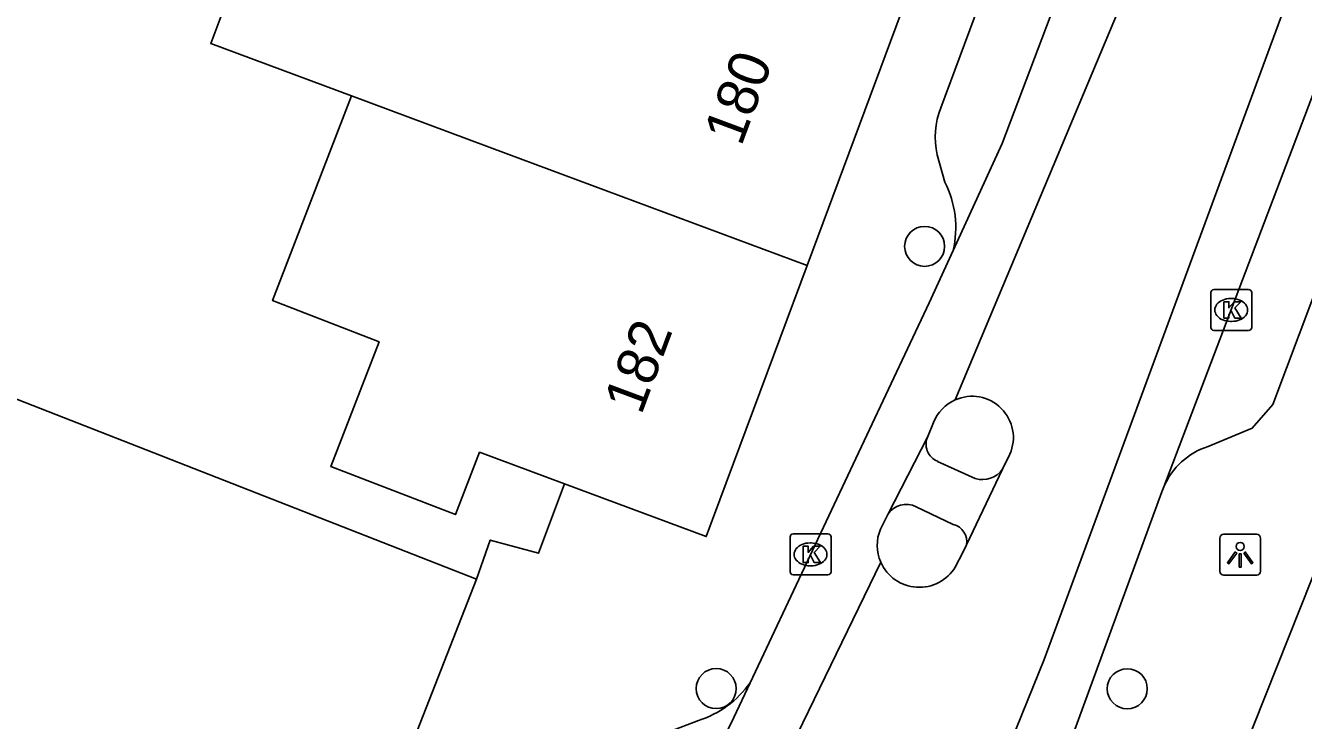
# Model space of a CAD drawing. Extents: x 160356 to 161355, y 381727 to 382845.
# Drawn here: x 160681.56 to 160712.78, y 382017.41 to 382034.4 of the extents above; entities that cross this region are included whole.
import ezdxf

# ---------------------------------------------------------------- set-up
doc = ezdxf.new("R2010")
doc.units = 0
for name, color, linetype in [('IMGEO_Boom', 7, 'Continuous'), ('IMGEO_Kolk', 7, 'Continuous'), ('IMGEO_Lichtpunt', 7, 'Continuous'), ('IMGEO_Pand', 7, 'Continuous'), ('IMGEO_Pand_nummerreeks', 7, 'Continuous'), ('IMGEO_Rijbaan_lokaal_gesloten', 7, 'Continuous'), ('IMGEO_Voetpad_open', 7, 'Continuous')]:
    doc.layers.add(name, color=color, linetype=linetype)

msp = doc.modelspace()

# ---------------------------------------------------------------- linework, layer by layer
at = {"layer": 'IMGEO_Boom'}
for centre in [(160703.526, 382029.002), (160698.432, 382018.193), (160708.478, 382018.188)]:
    msp.add_circle(centre, 0.489, dxfattribs=at)
at = {"layer": 'IMGEO_Kolk'}
for p, q in [((160710.593, 382027.947), (160711.445, 382027.947)), ((160710.518, 382027.021), (160710.518, 382027.873)), ((160711.006, 382027.727), (160711.031, 382027.727)), ((160711.519, 382027.873), (160711.519, 382027.021)), ((160711.029, 382027.167), (160711.004, 382027.167)), ((160711.445, 382026.947), (160710.593, 382026.947)), ((160700.238, 382021.047), (160700.238, 382021.899)), ((160700.313, 382021.973), (160701.165, 382021.973)), ((160700.726, 382021.753), (160700.751, 382021.753)), ((160701.239, 382021.899), (160701.239, 382021.047)), ((160700.749, 382021.193), (160700.724, 382021.193)), ((160701.165, 382020.973), (160700.313, 382020.973))]:
    msp.add_line(p, q, dxfattribs=at)
for points in [[(160710.593, 382027.947), (160711.445, 382027.947)], [(160710.518, 382027.021), (160710.518, 382027.873)], [(160710.839, 382027.647), (160710.962, 382027.647), (160710.962, 382027.496), (160711.092, 382027.647), (160711.256, 382027.647), (160711.11, 382027.496), (160711.263, 382027.247), (160711.111, 382027.247), (160711.026, 382027.411), (160710.962, 382027.344), (160710.962, 382027.247), (160710.839, 382027.247), (160710.839, 382027.647)], [(160711.519, 382027.873), (160711.519, 382027.021)], [(160711.445, 382026.947), (160710.593, 382026.947)], [(160700.238, 382021.047), (160700.238, 382021.899)], [(160700.313, 382021.973), (160701.165, 382021.973)], [(160701.239, 382021.899), (160701.239, 382021.047)], [(160700.559, 382021.673), (160700.682, 382021.673), (160700.682, 382021.522), (160700.812, 382021.673), (160700.976, 382021.673), (160700.83, 382021.522), (160700.983, 382021.273), (160700.831, 382021.273), (160700.746, 382021.437), (160700.682, 382021.37), (160700.682, 382021.273), (160700.559, 382021.273), (160700.559, 382021.673)], [(160701.165, 382020.973), (160700.313, 382020.973)]]:
    msp.add_lwpolyline(points, dxfattribs=at)
for centre, start, end in [((160710.595, 382027.871), 91.552, 178.448), ((160710.595, 382027.871), 91.552, 178.448), ((160711.443, 382027.871), 1.552, 88.448), ((160711.443, 382027.871), 1.552, 88.448), ((160710.595, 382027.023), 181.552, 268.448), ((160710.595, 382027.023), 181.552, 268.448), ((160711.443, 382027.023), 271.552, 358.448), ((160711.443, 382027.023), 271.552, 358.448), ((160700.315, 382021.897), 91.552, 178.448), ((160700.315, 382021.897), 91.552, 178.448), ((160701.163, 382021.897), 1.552, 88.448), ((160701.163, 382021.897), 1.552, 88.448), ((160700.315, 382021.049), 181.552, 268.448), ((160700.315, 382021.049), 181.552, 268.448), ((160701.163, 382021.049), 271.552, 358.448), ((160701.163, 382021.049), 271.552, 358.448)]:
    msp.add_arc(centre, 0.0765, start, end, dxfattribs=at)
for centre, major_axis, ratio, start_param, end_param in [((160711.005, 382027.447), (-0.387, 0.002), 0.722429, 4.712389, 7.853982), ((160711.03, 382027.447), (-0.39, 0.002), 0.717154, 1.570796, 4.712389), ((160700.725, 382021.473), (-0.387, 0.002), 0.722429, 4.712389, 7.853982), ((160700.75, 382021.473), (-0.39, 0.002), 0.717154, 1.570796, 4.712389)]:
    msp.add_ellipse(centre, major_axis=major_axis, ratio=ratio, start_param=start_param, end_param=end_param, dxfattribs=at)
at = {"layer": 'IMGEO_Lichtpunt'}
for p, q in [((160710.739, 382021.869), (160710.739, 382021.062)), ((160710.739, 382021.869), (160710.739, 382021.062)), ((160711.641, 382021.964), (160710.833, 382021.964)), ((160711.641, 382021.964), (160710.833, 382021.964)), ((160711.735, 382021.062), (160711.735, 382021.869)), ((160711.735, 382021.062), (160711.735, 382021.869)), ((160710.833, 382020.968), (160711.641, 382020.968)), ((160710.833, 382020.968), (160711.641, 382020.968))]:
    msp.add_line(p, q, dxfattribs=at)
for points in [[(160711.113, 382021.533), (160711.152, 382021.505), (160710.964, 382021.243), (160710.926, 382021.27), (160711.113, 382021.533)], [(160711.215, 382021.485), (160711.262, 382021.485), (160711.262, 382021.163), (160711.215, 382021.163), (160711.215, 382021.485)], [(160711.325, 382021.505), (160711.363, 382021.532), (160711.55, 382021.27), (160711.511, 382021.242), (160711.325, 382021.505)]]:
    msp.add_lwpolyline(points, dxfattribs=at)
msp.add_circle((160711.238, 382021.667), 0.0994, dxfattribs=at)
for centre, start, end in [((160710.833, 382021.869), 90, 180), ((160710.833, 382021.869), 90, 180), ((160711.641, 382021.869), 0, 90), ((160711.641, 382021.869), 0, 90), ((160710.833, 382021.062), 180, 270), ((160710.833, 382021.062), 180, 270), ((160711.641, 382021.062), 270, 0), ((160711.641, 382021.062), 270, 360)]:
    msp.add_arc(centre, 0.0946, start, end, dxfattribs=at)
at = {"layer": 'IMGEO_Pand'}
for points in [[(160660.842, 382040.237), (160659.757, 382037.624), (160654.494, 382039.809), (160653.852, 382036.7), (160654.668, 382036.531), (160653.948, 382033.048), (160653.21, 382033.201), (160652.031, 382030.186), (160664.979, 382025.121), (160667.199, 382030.796), (160678.768, 382026.27), (160684.128, 382024.173), (160692.577, 382020.868)], [(160691.727, 382039.294), (160690.193, 382035.169), (160688.694, 382035.727), (160686.815, 382035.925), (160686.083, 382033.957), (160689.52, 382032.679)], [(160700.657, 382028.536), (160703.087, 382035.068)], [(160689.52, 382032.679), (160687.591, 382027.678), (160690.197, 382026.672), (160689.019, 382023.617), (160692.06, 382022.444), (160692.649, 382023.969), (160694.723, 382023.198)], [(160700.657, 382028.536), (160693.3, 382031.273), (160689.52, 382032.679)], [(160694.723, 382023.198), (160698.192, 382021.908), (160700.657, 382028.536)], [(160686.323, 382008.467), (160687.207, 382010.728), (160688.566, 382014.202), (160687.548, 382014.601), (160688.056, 382015.9), (160690.292, 382015.025), (160690.483, 382015.514), (160692.577, 382020.868)]]:
    msp.add_lwpolyline(points, dxfattribs=at)
at = {"layer": 'IMGEO_Rijbaan_lokaal_gesloten'}
for points in [[(160704.275, 382025.25), (160710.123, 382039.204), (160720.494, 382066.374), (160724.887, 382077.653), (160727.444, 382083.882), (160731.871, 382093.997), (160742.756, 382117.768), (160747.076, 382126.71), (160748.813, 382130.153), (160751.633, 382135.727), (160755.42, 382142.776), (160760.731, 382152.677), (160766.428, 382162.546), (160770.494, 382169.628), (160769.164, 382170.249)], [(160774.485, 382166.436), (160773.018, 382167.169), (160767.084, 382156.956), (160759.953, 382144.071), (160758.33, 382141.071), (160754.903, 382134.448), (160748.477, 382121.661), (160743.231, 382110.677), (160737.526, 382098.251), (160733.461, 382089.005), (160728.018, 382076.284), (160718.969, 382052.415), (160712.871, 382036.35), (160706.444, 382018.907), (160701.297, 382006.186), (160702.724, 382005.472)], [(160747.213, 382130.437), (160738.5, 382112.538), (160731.504, 382097.136), (160724.098, 382079.993), (160717.39, 382062.79), (160711.373, 382047.241), (160705.42, 382031.515), (160704.223, 382028.902)], [(160709.375, 382023.124), (160713.284, 382033.416), (160713.707, 382034.733), (160721.146, 382054.264)], [(160704.223, 382028.902), (160703.636, 382027.62), (160699.26, 382018.335)], [(160703.607, 382024.358), (160703.747, 382024.699)], [(160702.626, 382022.447), (160703.607, 382024.358)], [(160705.433, 382023.557), (160705.609, 382023.921)], [(160705.433, 382023.557), (160704.546, 382021.704)], [(160704.168, 382009.251), (160704.765, 382010.743), (160706.286, 382014.7), (160709.327, 382022.999), (160709.375, 382023.124)], [(160702.448, 382022.093), (160702.626, 382022.447)], [(160704.275, 382021.164), (160704.459, 382021.523), (160704.546, 382021.704)], [(160693.954, 382007.485), (160695.412, 382006.702), (160700.139, 382016.515), (160702.456, 382021.28)], [(160699.26, 382018.335), (160698.861, 382017.487), (160693.954, 382007.485)]]:
    msp.add_lwpolyline(points, dxfattribs=at)
for centre, radius, start, end in [((160704.688, 382024.325), 1.013, 114.0907, 158.3515), ((160704.685, 382024.327), 1.01, 336.2562, 113.9589), ((160703.394, 382021.696), 1.026, 157.2139, 203.9137), ((160703.396, 382021.696), 1.028, 203.8879, 328.8144)]:
    msp.add_arc(centre, radius, start, end, dxfattribs=at)
at = {"layer": 'IMGEO_Voetpad_open'}
for points in [[(160707.027, 382005.872), (160723.769, 382047.981), (160723.909, 382047.851), (160734.483, 382073.75), (160746.148, 382100.741), (160750.887, 382111.2), (160755.847, 382121.079), (160757.838, 382125.044), (160765.277, 382139.388)], [(160703.919, 382032.385), (160710.641, 382050.478), (160716.296, 382065.22), (160720.616, 382076.203), (160724.822, 382086.526), (160726.382, 382090.148)], [(160721.637, 382050.795), (160714.942, 382032.865), (160712.034, 382025.14), (160711.531, 382024.56), (160710.453, 382024.108)], [(160704.02, 382030.569), (160703.83, 382031.242)], [(160703.845, 382023.747), (160704.764, 382023.327)], [(160692.577, 382020.868), (160692.91, 382021.824), (160694.093, 382021.5), (160694.723, 382023.198)], [(160704.226, 382022.205), (160703.322, 382022.636)], [(160697.998, 382017.414), (160697.274, 382017.135)]]:
    msp.add_lwpolyline(points, dxfattribs=at)
for centre, radius, start, end in [((160705.813, 382031.663), 2.027, 159.1179, 191.9774), ((160701.873, 382029.462), 2.415, 346.601, 27.2851), ((160704.007, 382024.162), 0.445, 153.8829, 248.6814), ((160710.982, 382022.446), 1.745, 107.6634, 157.1163), ((160704.941, 382023.901), 0.6, 252.8729, 325.0727), ((160703.077, 382022.163), 0.533, 62.6289, 147.7559), ((160704.13, 382021.791), 0.425, 348.194, 76.9406), ((160697.275, 382019.73), 2.426, 287.3371, 324.9064)]:
    msp.add_arc(centre, radius, start, end, dxfattribs=at)

# ---------------------------------------------------------------- texts
at = {"layer": 'IMGEO_Pand_nummerreeks'}
for s, p in [('180', (160699.043, 382031.424)), ('182', (160696.601, 382024.858))]:
    msp.add_text(s, height=1, rotation=69.5972, dxfattribs=at).set_placement(p)

doc.saveas('drawing.dxf')
